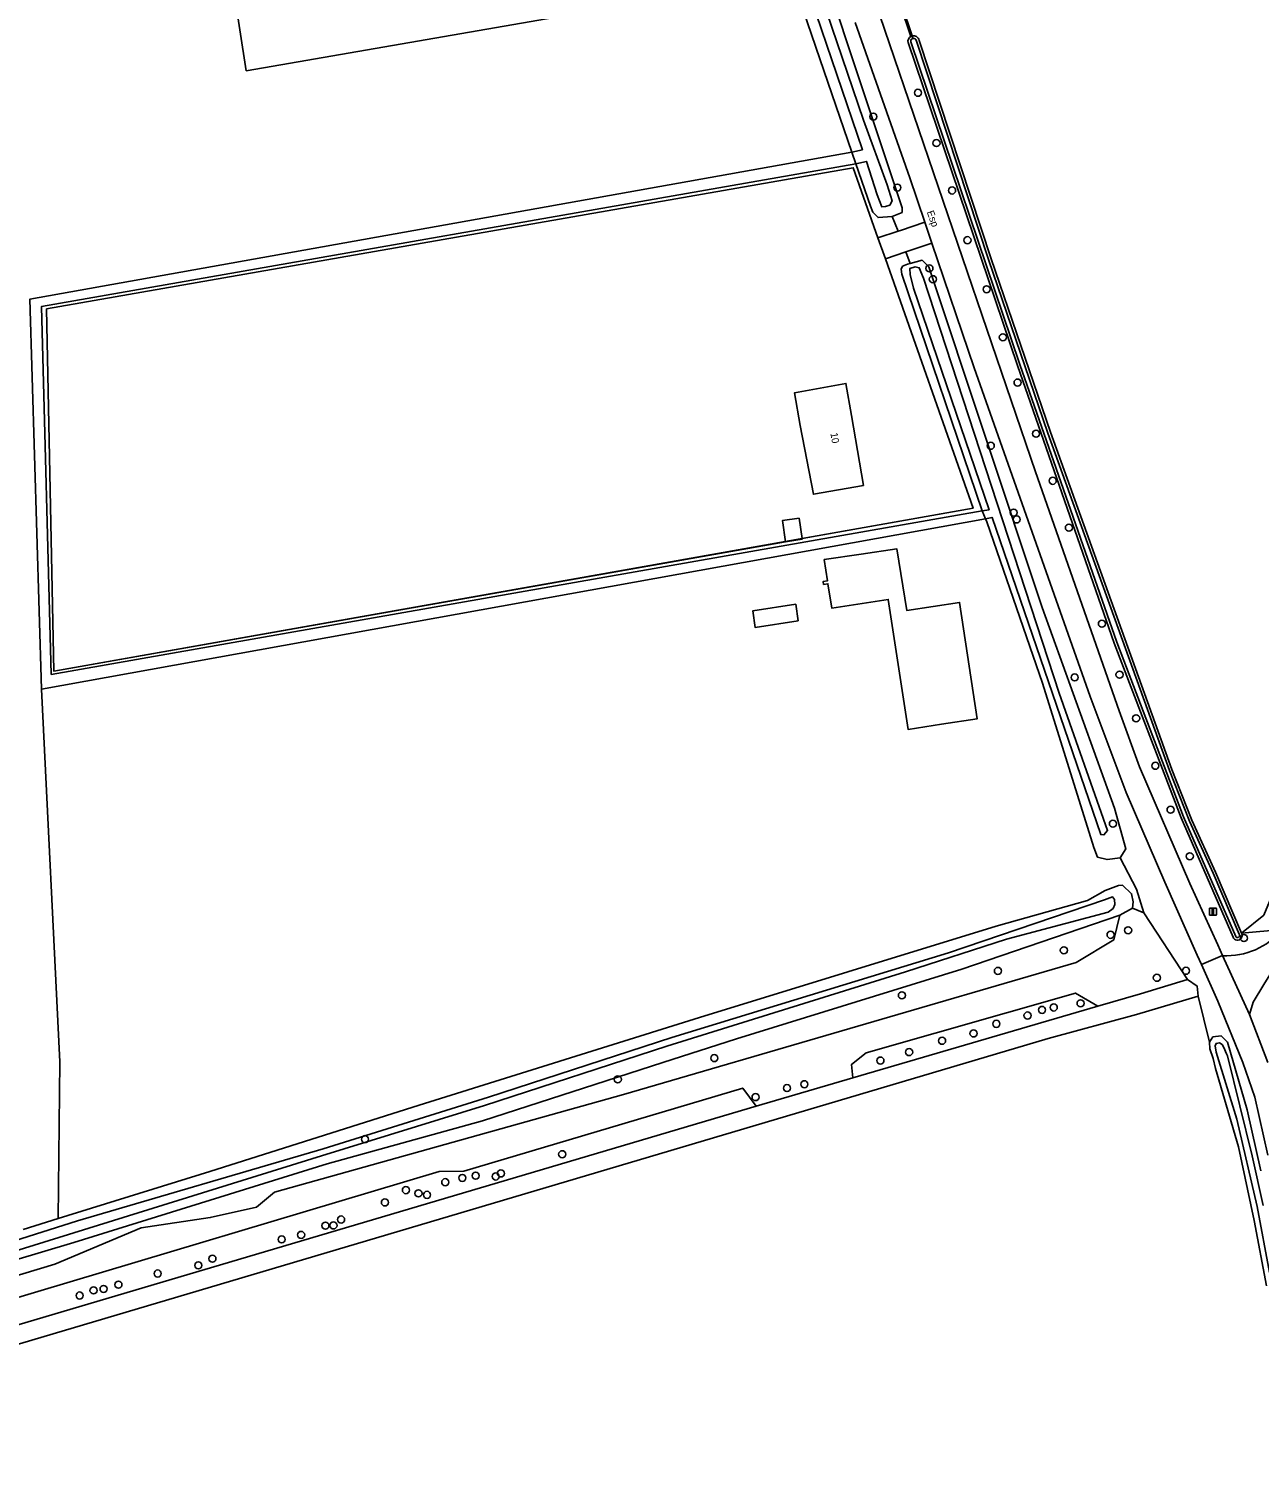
# Model space of a CAD drawing. Extents: x 161385 to 162589, y 388479 to 389756.
# Drawn here: x 161634.8 to 161804.9, y 389443.5 to 389642.9 of the extents above; entities that cross this region are included whole.
import ezdxf

# ---------------------------------------------------------------- set-up
doc = ezdxf.new("R2010")
doc.units = 0
for name, color, linetype in [('IMGEO_Boom', 7, 'Continuous'), ('IMGEO_Bouwland', 7, 'Continuous'), ('IMGEO_Duiker', 7, 'Continuous'), ('IMGEO_Erf', 7, 'Continuous'), ('IMGEO_Grasland_overig', 7, 'Continuous'), ('IMGEO_Groenvoorziening', 7, 'Continuous'), ('IMGEO_Hek', 7, 'Continuous'), ('IMGEO_Loofbos', 7, 'Continuous'), ('IMGEO_Oever', 7, 'Continuous'), ('IMGEO_Openbare_ruimte_label', 7, 'Continuous'), ('IMGEO_Pand', 7, 'Continuous'), ('IMGEO_Pand_nummerreeks', 7, 'Continuous'), ('IMGEO_Rijbaan_lokaal_gesloten', 7, 'Continuous'), ('IMGEO_Verkeersbordpaal', 7, 'Continuous'), ('IMGEO_Voetpad_halfverhard', 7, 'Continuous'), ('IMGEO_Waterloop', 7, 'Continuous')]:
    doc.layers.add(name, color=color, linetype=linetype)

msp = doc.modelspace()

# ---------------------------------------------------------------- linework, layer by layer
at = {"layer": 'IMGEO_Boom'}
for centre in [(161757.77, 389634.09), (161751.6, 389630.79), (161760.33, 389627.14), (161754.92, 389620.98), (161762.49, 389620.58), (161764.62, 389613.71), (161759.36, 389609.81), (161759.83, 389608.31), (161767.26, 389606.92), (161769.51, 389600.28), (161771.54, 389594.02), (161774.1, 389586.95), (161767.84, 389585.28), (161776.41, 389580.43), (161771, 389576.03), (161771.42, 389575.09), (161778.64, 389573.95), (161783.2, 389560.67), (161779.44, 389553.25), (161785.64, 389553.62), (161787.94, 389547.59), (161790.6, 389541.03), (161792.7, 389534.95), (161784.72, 389533.01), (161795.36, 389528.51), (161786.83, 389518.28), (161784.4, 389517.65), (161802.83, 389517.2), (161777.94, 389515.51), (161768.82, 389512.66), (161794.83, 389512.68), (161790.8, 389511.71), (161755.55, 389509.28), (161780.25, 389508.18), (161772.92, 389506.49), (161774.93, 389507.27), (161776.55, 389507.6), (161768.61, 389505.34), (161761.11, 389503), (161765.45, 389504.01), (161729.61, 389500.6), (161752.58, 389500.26), (161756.55, 389501.43), (161716.27, 389497.66), (161739.66, 389496.46), (161742.07, 389496.99), (161735.32, 389495.21), (161681.31, 389489.39), (161708.58, 389487.31), (161696.62, 389484.34), (161700.11, 389484.65), (161686.97, 389482.34), (161692.41, 389483.44), (161694.77, 389484.03), (161699.39, 389484.23), (161684.07, 389480.64), (161688.71, 389481.9), (161689.89, 389481.69), (161678.01, 389478.28), (161675.85, 389477.43), (161676.96, 389477.46), (161669.79, 389475.53), (161672.49, 389476.15), (161660.22, 389472.86), (161652.65, 389470.81), (161658.27, 389471.94), (161643.78, 389468.48), (161645.17, 389468.68), (161647.23, 389469.27), (161641.86, 389467.77)]:
    msp.add_circle(centre, 0.489, dxfattribs=at)
at = {"layer": 'IMGEO_Bouwland'}
for points in [[(161755.35, 389646.1), (161756.8, 389641.89), (161756.96, 389641.96)], [(161757.92, 389641.33), (161767.87, 389611.14), (161776.09, 389587.15), (161792.89, 389540.49), (161795.64, 389533.52), (161798.92, 389526.32), (161802.52, 389517.87), (161805.58, 389520.38), (161823.14, 389562.68), (161834.74, 389593.08), (161850.18, 389632.62)], [(161805.95, 389469.11), (161804.25, 389478.14), (161802.1, 389488.34), (161798.9, 389499.15), (161798.57, 389500.56), (161798.13, 389501.88), (161798.1, 389502.8), (161796.49, 389509.15), (161787.98, 389506.65), (161775.79, 389503.31), (161622.16, 389457.73), (161624.51, 389453.44), (161631.46, 389441.6)]]:
    msp.add_lwpolyline(points, dxfattribs=at)
msp.add_arc((161757.16, 389641.22), 0.768, 8.2045, 105.079, dxfattribs=at)
at = {"layer": 'IMGEO_Duiker'}
msp.add_lwpolyline([(161755.48, 389646.33), (161755.52, 389646.21), (161756.96, 389641.96), (161757.07, 389641.66)], dxfattribs=at)
at = {"layer": 'IMGEO_Erf'}
for points in [[(161753.26, 389611.13), (161752.24, 389614.01), (161748.82, 389623.73), (161637.3, 389604.2), (161638.28, 389554.11), (161739.46, 389572.01), (161739.03, 389574.93), (161741.33, 389575.26), (161741.74, 389572.44), (161765.39, 389576.63)], [(161741.49, 389588.1), (161740.68, 389592.59), (161747.8, 389593.9), (161748.59, 389589.45), (161750.23, 389579.8), (161743.32, 389578.57)], [(161787.44, 389521.34), (161788.98, 389520.71), (161788, 389523.94), (161785.74, 389528.31), (161783.93, 389528.06), (161782.59, 389528.39), (161782.09, 389529.72), (161774.99, 389552.47), (161773.25, 389557.51), (161767.29, 389574.78), (161767.12, 389575.17), (161636.58, 389551.64), (161639.11, 389500.1), (161638.91, 389478.41), (161659.87, 389484.9), (161688.79, 389494.08), (161727.57, 389506.22), (161768.6, 389518.85), (161781.2, 389522.41), (161783.65, 389523.76), (161785.49, 389524.49), (161786.04, 389524.5), (161787.31, 389523.32), (161787.52, 389522.19)], [(161749.93, 389570.28), (161754.87, 389571.01), (161756.21, 389562.5), (161763.52, 389563.62), (161765.97, 389547.52), (161761.02, 389546.76), (161756.41, 389546.06), (161753.67, 389564.03), (161745.84, 389562.84), (161745.32, 389566.2), (161744.73, 389566.11), (161744.67, 389566.51), (161745.26, 389566.6), (161744.81, 389569.53)], [(161741.23, 389561.06), (161735.28, 389560.13), (161734.92, 389562.43), (161740.87, 389563.36)]]:
    msp.add_lwpolyline(points, close=True, dxfattribs=at)
at = {"layer": 'IMGEO_Grasland_overig'}
for points in [[(161707.62, 389676.36), (161660.1, 389668.21), (161664.89, 389637.14), (161713.62, 389645.57), (161708.55, 389671.57)], [(161756.68, 389610.47), (161756.1, 389612.09), (161753.26, 389611.13), (161765.39, 389576.63), (161741.74, 389572.44), (161741.76, 389572.35), (161739.46, 389572.01), (161638.28, 389554.11), (161637.3, 389604.2), (161748.82, 389623.73), (161752.24, 389614.01), (161755.04, 389614.95), (161754.19, 389616.97), (161752.25, 389616.83), (161751.51, 389617.56), (161751.21, 389618.42), (161749.2, 389624.28), (161636.59, 389604.55), (161637.93, 389553.66), (161766.66, 389576.3), (161755.52, 389609), (161755.44, 389609.69), (161755.65, 389610.11), (161756.33, 389610.41)]]:
    msp.add_lwpolyline(points, close=True, dxfattribs=at)
msp.add_lwpolyline([(161631.17, 389466.87), (161691.55, 389484.94), (161694.97, 389484.95), (161733.55, 389496.45), (161735.39, 389493.94), (161748.75, 389497.85), (161748.6, 389499.73), (161750.62, 389501.33), (161779.55, 389509.59), (161782.64, 389507.78), (161788.56, 389509.51), (161795.03, 389511.46), (161788.98, 389520.71), (161787.44, 389521.34), (161785.68, 389520.39), (161784.85, 389516.94), (161779.63, 389513.83), (161717.05, 389495.56), (161668.81, 389482.06), (161666.31, 389479.98), (161659.91, 389478.55), (161650.36, 389477.13), (161638.43, 389472.12), (161627.11, 389468.69)], dxfattribs=at)
at = {"layer": 'IMGEO_Groenvoorziening'}
for points in [[(161739.11, 389695.48), (161737.94, 389699.89), (161728.25, 389730.77), (161728.21, 389731.71), (161728.61, 389731.67), (161728.09, 389733.49), (161724.89, 389732.65), (161726.2, 389729.06), (161730.02, 389717.53), (161734.76, 389700.98), (161750.45, 389650.77), (161774.03, 389581.66), (161785.58, 389548.61), (161788.41, 389540.88), (161795.35, 389524.74), (161799.21, 389516.27), (161799.9, 389514.77)], [(161736.37, 389676.66), (161747.76, 389641.67), (161755.61, 389618.2), (161755.57, 389617.55), (161754.19, 389616.97), (161755.04, 389614.95), (161755.34, 389615.05), (161758.73, 389616.19), (161756.66, 389622.34), (161749.1, 389643.81)], [(161756.8, 389641.89), (161755.35, 389646.1)], [(161801.33, 389517.34), (161794.14, 389533.83), (161784.9, 389558), (161771.52, 389596.38), (161756.42, 389641.03)], [(161806.16, 389487.18), (161804.33, 389495.22), (161802.71, 389500), (161799.22, 389508.46), (161796.96, 389513.54), (161796.38, 389514.84), (161791.89, 389524.92), (161786.55, 389537.33), (161781.58, 389550.59), (161765.52, 389596.05), (161759.71, 389613.3), (161756.39, 389612.19), (161756.1, 389612.09), (161756.68, 389610.47), (161758.36, 389610.93), (161759.27, 389610.01), (161774.96, 389562.93), (161784.95, 389535.18), (161786.51, 389529.55), (161785.74, 389528.31), (161788, 389523.94), (161788.98, 389520.71), (161795.03, 389511.46), (161796.36, 389510.57), (161796.49, 389509.15), (161798.1, 389502.8), (161798.56, 389503.54), (161799.69, 389503.66), (161800.59, 389502.81), (161803.28, 389493.46), (161805.17, 389485)], [(161808.11, 389518.37), (161802.52, 389517.87)], [(161805.6, 389510.78), (161804.1, 389508.35), (161803.61, 389506.63), (161806.15, 389500)]]:
    msp.add_lwpolyline(points, dxfattribs=at)
for centre, radius, start, end in [((161757.16, 389641.21), 0.77, 118.4453, 194.0735), ((161800.44, 389524.71), 9.96, 266.9061, 320.4376), ((161801.95, 389517.56), 0.653, 199.6974, 28.5135)]:
    msp.add_arc(centre, radius, start, end, dxfattribs=at)
at = {"layer": 'IMGEO_Hek'}
for points in [[(161638.28, 389554.11), (161637.3, 389604.2), (161748.82, 389623.73), (161752.24, 389614.01)], [(161752.24, 389614.01), (161753.26, 389611.13)], [(161753.26, 389611.13), (161765.39, 389576.63), (161638.28, 389554.11)]]:
    msp.add_lwpolyline(points, dxfattribs=at)
at = {"layer": 'IMGEO_Loofbos'}
for points in [[(161894.5, 389744.39), (161882.99, 389714.22), (161877.85, 389700.76), (161850.18, 389632.62), (161834.74, 389593.08), (161823.14, 389562.68), (161805.58, 389520.38), (161802.52, 389517.87), (161808.11, 389518.37), (161812.66, 389525.18), (161820.8, 389546.37), (161840, 389592.74), (161845.22, 389606.21), (161851.87, 389624.85), (161861.68, 389650.87), (161883.03, 389700.95), (161900.75, 389744.5), (161896.87, 389744.43)], [(161623.96, 389469.28), (161624.71, 389468.96), (161625.49, 389468.75), (161626.3, 389468.66), (161627.11, 389468.69), (161638.43, 389472.12), (161650.36, 389477.13), (161659.91, 389478.55), (161666.31, 389479.98), (161668.81, 389482.06), (161717.05, 389495.56), (161779.63, 389513.83), (161784.85, 389516.94), (161785.68, 389520.39), (161763.85, 389512.88), (161732.67, 389503.28), (161722.51, 389500), (161697.56, 389491.94), (161676.08, 389485.99), (161641.06, 389475.11), (161624.05, 389470.05), (161623.02, 389469.89)], [(161782.64, 389507.78), (161779.55, 389509.59), (161750.62, 389501.33), (161748.6, 389499.73), (161748.75, 389497.85)], [(161735.39, 389493.94), (161733.55, 389496.45), (161694.97, 389484.95), (161691.55, 389484.94), (161631.17, 389466.87), (161619.26, 389462.6), (161620.01, 389461.44), (161620.99, 389460.08)]]:
    msp.add_lwpolyline(points, close=True, dxfattribs=at)
for points in [[(161713.62, 389645.57), (161664.89, 389637.14), (161660.1, 389668.21)], [(161634.05, 389476.9), (161638.91, 389478.41), (161639.11, 389500.1), (161636.58, 389551.64), (161634.96, 389605.53), (161748.65, 389625.88), (161738.61, 389655.09)]]:
    msp.add_lwpolyline(points, dxfattribs=at)
at = {"layer": 'IMGEO_Oever'}
for points in [[(161734.87, 389675.57), (161750.24, 389630.32), (161753.51, 389621.34), (161754.2, 389619.15), (161753.88, 389618.57), (161753.27, 389618.38), (161752.77, 389618.33), (161752.11, 389619.99), (161750.64, 389624.61), (161749.2, 389624.28), (161751.21, 389618.42), (161751.51, 389617.56), (161752.25, 389616.83), (161754.19, 389616.97), (161755.57, 389617.55), (161755.61, 389618.2), (161747.76, 389641.67), (161736.37, 389676.66)], [(161738.61, 389655.09), (161748.65, 389625.88), (161750.09, 389626.21), (161739.44, 389657.48)], [(161756.42, 389641.03), (161771.52, 389596.38), (161784.9, 389558), (161794.14, 389533.83), (161801.33, 389517.34)], [(161801.7, 389517.42), (161794.48, 389533.97), (161785.25, 389558.13), (161771.87, 389596.5), (161756.78, 389641.12)], [(161756.96, 389641.96), (161756.8, 389641.89)], [(161757.48, 389641.46), (161757.57, 389641.23), (161767.52, 389611.02), (161775.74, 389587.02), (161792.55, 389540.36), (161795.3, 389533.38), (161798.58, 389526.17), (161802.18, 389517.73), (161802.22, 389517.65)], [(161767.87, 389611.14), (161757.92, 389641.33)], [(161802.52, 389517.87), (161798.92, 389526.32), (161795.64, 389533.52), (161792.89, 389540.49), (161776.09, 389587.15), (161767.87, 389611.14)], [(161624.05, 389470.05), (161641.06, 389475.11), (161676.08, 389485.99), (161697.56, 389491.94), (161722.51, 389500), (161732.67, 389503.28), (161763.85, 389512.88), (161785.68, 389520.39), (161787.44, 389521.34), (161787.52, 389522.19), (161787.31, 389523.32), (161786.04, 389524.5), (161785.49, 389524.49), (161783.65, 389523.76), (161781.2, 389522.41), (161768.6, 389518.85), (161727.57, 389506.22), (161688.79, 389494.08), (161659.87, 389484.9), (161638.91, 389478.41), (161634.05, 389476.9)], [(161624.99, 389472.83), (161641.57, 389478.1), (161675.52, 389488.05), (161698.39, 389495.19), (161723.76, 389503.45), (161762.01, 389515.17), (161783.54, 389522.48), (161784.69, 389522.88), (161784.94, 389522.53), (161785.01, 389521.85), (161784.75, 389521.3), (161784.09, 389520.77), (161770.02, 389517.03), (161756.06, 389512.51), (161723.05, 389502.24), (161697.85, 389494.06), (161675.31, 389487.07), (161624.57, 389471.33)], [(161805.17, 389485), (161803.28, 389493.46), (161800.59, 389502.81), (161799.69, 389503.66), (161798.56, 389503.54), (161798.1, 389502.8), (161798.13, 389501.88), (161798.57, 389500.56), (161798.9, 389499.15), (161802.1, 389488.34), (161804.25, 389478.14), (161805.95, 389469.11)], [(161806.38, 389470.95), (161804.69, 389480.06), (161801.86, 389492.16), (161799.01, 389501.42), (161798.86, 389502.31), (161798.99, 389502.64), (161799.47, 389502.72), (161799.81, 389502.5), (161800.05, 389502.08), (161800.45, 389501.19), (161800.55, 389500.9), (161803.98, 389487.09), (161805.48, 389480.24)]]:
    msp.add_lwpolyline(points, dxfattribs=at)
msp.add_lwpolyline([(161757.16, 389607.08), (161756.68, 389608.96), (161756.63, 389609.78), (161757.37, 389610.02), (161757.95, 389609.89), (161758.54, 389608.46), (161777.28, 389551.05), (161783.98, 389532.09), (161783.49, 389531.46), (161783.04, 389531.52), (161768.01, 389575.38), (161767.12, 389575.17), (161767.29, 389574.78), (161773.25, 389557.51), (161774.99, 389552.47), (161782.09, 389529.72), (161782.59, 389528.39), (161783.93, 389528.06), (161785.74, 389528.31), (161786.51, 389529.55), (161784.95, 389535.18), (161774.96, 389562.93), (161759.27, 389610.01), (161758.36, 389610.93), (161756.68, 389610.47), (161756.33, 389610.41), (161755.65, 389610.11), (161755.44, 389609.69), (161755.52, 389609), (161766.66, 389576.3), (161767.61, 389576.43)], close=True, dxfattribs=at)
for centre, radius, start, end in [((161757.16, 389641.21), 0.77, 118.4453, 194.0735), ((161757.16, 389641.21), 0.398, 37.3635, 194.125), ((161757.16, 389641.22), 0.768, 8.2045, 105.079), ((161801.95, 389517.56), 0.653, 199.6974, 28.5135), ((161801.95, 389517.56), 0.283, 210.0651, 18.1492)]:
    msp.add_arc(centre, radius, start, end, dxfattribs=at)
at = {"layer": 'IMGEO_Pand'}
for points in [[(161743.32, 389578.57), (161750.23, 389579.8), (161748.59, 389589.45), (161747.8, 389593.9), (161740.68, 389592.59), (161741.49, 389588.1)], [(161739.03, 389574.93), (161739.46, 389572.01), (161741.76, 389572.35), (161741.74, 389572.44), (161741.33, 389575.26)], [(161749.93, 389570.28), (161744.81, 389569.53), (161745.26, 389566.6), (161744.67, 389566.51), (161744.73, 389566.11), (161745.32, 389566.2), (161745.84, 389562.84), (161753.67, 389564.03), (161756.41, 389546.06), (161761.02, 389546.76), (161765.97, 389547.52), (161763.52, 389563.62), (161756.21, 389562.5), (161754.87, 389571.01)], [(161741.23, 389561.06), (161740.87, 389563.36), (161734.92, 389562.43), (161735.28, 389560.13)]]:
    msp.add_lwpolyline(points, close=True, dxfattribs=at)
at = {"layer": 'IMGEO_Rijbaan_lokaal_gesloten'}
for points in [[(161749.1, 389643.81), (161756.66, 389622.34), (161758.73, 389616.19), (161759.71, 389613.3), (161765.52, 389596.05), (161781.58, 389550.59), (161786.55, 389537.33), (161791.89, 389524.92), (161796.38, 389514.84), (161796.96, 389513.54), (161799.9, 389514.77), (161799.21, 389516.27), (161795.35, 389524.74), (161788.41, 389540.88), (161785.58, 389548.61), (161774.03, 389581.66), (161750.45, 389650.77)], [(161806.15, 389500), (161803.61, 389506.63), (161799.9, 389514.77), (161796.96, 389513.54), (161799.22, 389508.46), (161802.71, 389500), (161804.33, 389495.22), (161806.16, 389487.18)]]:
    msp.add_lwpolyline(points, dxfattribs=at)
msp.add_lwpolyline([(161756.1, 389612.09), (161756.39, 389612.19), (161759.71, 389613.3), (161758.73, 389616.19), (161755.34, 389615.05), (161755.04, 389614.95), (161752.24, 389614.01), (161753.26, 389611.13)], close=True, dxfattribs=at)
at = {"layer": 'IMGEO_Verkeersbordpaal'}
for p, q in [((161798.06, 389520.45), (161798.06, 389521.25)), ((161798.06, 389521.25), (161798.06, 389520.45)), ((161798.16, 389521.35), (161798.94, 389521.35)), ((161798.94, 389521.35), (161798.16, 389521.35)), ((161799.04, 389521.25), (161799.04, 389520.45)), ((161799.04, 389520.45), (161799.04, 389521.25)), ((161798.94, 389520.35), (161798.16, 389520.35)), ((161798.16, 389520.35), (161798.94, 389520.35))]:
    msp.add_line(p, q, dxfattribs=at)
msp.add_lwpolyline([(161798.47, 389521.23), (161798.62, 389521.23), (161798.62, 389520.48), (161798.47, 389520.48), (161798.47, 389521.23)], dxfattribs=at)
for centre, start, end in [((161798.16, 389521.25), 90, 180), ((161798.16, 389521.25), 90, 180), ((161798.94, 389521.25), 0, 90), ((161798.94, 389521.25), 360, 90), ((161798.16, 389520.45), 180, 270), ((161798.16, 389520.45), 180, 270), ((161798.94, 389520.45), 270, 0), ((161798.94, 389520.45), 270, 0)]:
    msp.add_arc(centre, 0.1, start, end, dxfattribs=at)
at = {"layer": 'IMGEO_Voetpad_halfverhard'}
msp.add_lwpolyline([(161799.9, 389514.77), (161803.61, 389506.63), (161804.1, 389508.35), (161805.6, 389510.78), (161806.89, 389512.86), (161809.44, 389517.66), (161814.32, 389524.91), (161827.75, 389558.76), (161835.72, 389579.02), (161841.61, 389592.08), (161852.36, 389621.86), (161862.59, 389646.34), (161871.15, 389667.84), (161878.53, 389684.99), (161884.85, 389700.35), (161903.45, 389744.54), (161900.75, 389744.5)], dxfattribs=at)
msp.add_arc((161800.44, 389524.71), 9.96, 266.9061, 320.4376, dxfattribs=at)
at = {"layer": 'IMGEO_Waterloop'}
for points in [[(161734.87, 389675.57), (161734.42, 389676.41), (161733.81, 389676.62), (161732.91, 389676.31), (161732.81, 389675.75), (161734.08, 389672.55), (161739.44, 389657.48), (161750.09, 389626.21), (161748.65, 389625.88), (161749.2, 389624.28), (161750.64, 389624.61), (161752.11, 389619.99), (161752.77, 389618.33), (161753.27, 389618.38), (161753.88, 389618.57), (161754.2, 389619.15), (161753.51, 389621.34), (161750.24, 389630.32)], [(161636.59, 389604.55), (161749.2, 389624.28), (161748.65, 389625.88), (161634.96, 389605.53), (161636.58, 389551.64), (161767.12, 389575.17), (161766.66, 389576.3), (161637.93, 389553.66)], [(161758.54, 389608.46), (161757.95, 389609.89), (161757.37, 389610.02), (161756.63, 389609.78), (161756.68, 389608.96), (161757.16, 389607.08), (161767.61, 389576.43), (161766.66, 389576.3), (161767.12, 389575.17), (161768.01, 389575.38), (161783.04, 389531.52), (161783.49, 389531.46), (161783.98, 389532.09), (161777.28, 389551.05)], [(161620.99, 389460.08), (161621.42, 389459.21), (161622.16, 389457.73), (161775.79, 389503.31), (161787.98, 389506.65), (161796.49, 389509.15), (161796.36, 389510.57), (161795.03, 389511.46), (161788.56, 389509.51), (161782.64, 389507.78), (161748.75, 389497.85), (161735.39, 389493.94)]]:
    msp.add_lwpolyline(points, close=True, dxfattribs=at)
for points in [[(161756.78, 389641.12), (161771.87, 389596.5), (161785.25, 389558.13), (161794.48, 389533.97), (161801.7, 389517.42)], [(161767.52, 389611.02), (161757.57, 389641.23), (161757.48, 389641.46)], [(161802.22, 389517.65), (161802.18, 389517.73), (161798.58, 389526.17), (161795.3, 389533.38), (161792.55, 389540.36), (161775.74, 389587.02), (161767.52, 389611.02)], [(161624.57, 389471.33), (161675.31, 389487.07), (161697.85, 389494.06), (161723.05, 389502.24), (161756.06, 389512.51), (161770.02, 389517.03), (161784.09, 389520.77), (161784.75, 389521.3), (161785.01, 389521.85), (161784.94, 389522.53), (161784.69, 389522.88), (161783.54, 389522.48), (161762.01, 389515.17), (161723.76, 389503.45), (161698.39, 389495.19), (161675.52, 389488.05), (161641.57, 389478.1), (161624.99, 389472.83)], [(161805.48, 389480.24), (161803.98, 389487.09), (161800.55, 389500.9), (161800.45, 389501.19), (161800.05, 389502.08), (161799.81, 389502.5), (161799.47, 389502.72), (161798.99, 389502.64), (161798.86, 389502.31), (161799.01, 389501.42), (161801.86, 389492.16), (161804.69, 389480.06), (161806.38, 389470.95)]]:
    msp.add_lwpolyline(points, dxfattribs=at)
for centre, radius, start, end in [((161757.16, 389641.21), 0.398, 37.3635, 194.125), ((161801.95, 389517.56), 0.283, 210.0651, 18.1492)]:
    msp.add_arc(centre, radius, start, end, dxfattribs=at)

# ---------------------------------------------------------------- texts
at = {"layer": 'IMGEO_Openbare_ruimte_label'}
msp.add_text('Esp', height=1, rotation=290.0663, dxfattribs=at).set_placement((161758.97, 389617.6))
at = {"layer": 'IMGEO_Pand_nummerreeks'}
msp.add_text('10', height=1, rotation=279.7711, dxfattribs=at).set_placement((161745.66, 389587.01))

doc.saveas('drawing.dxf')
